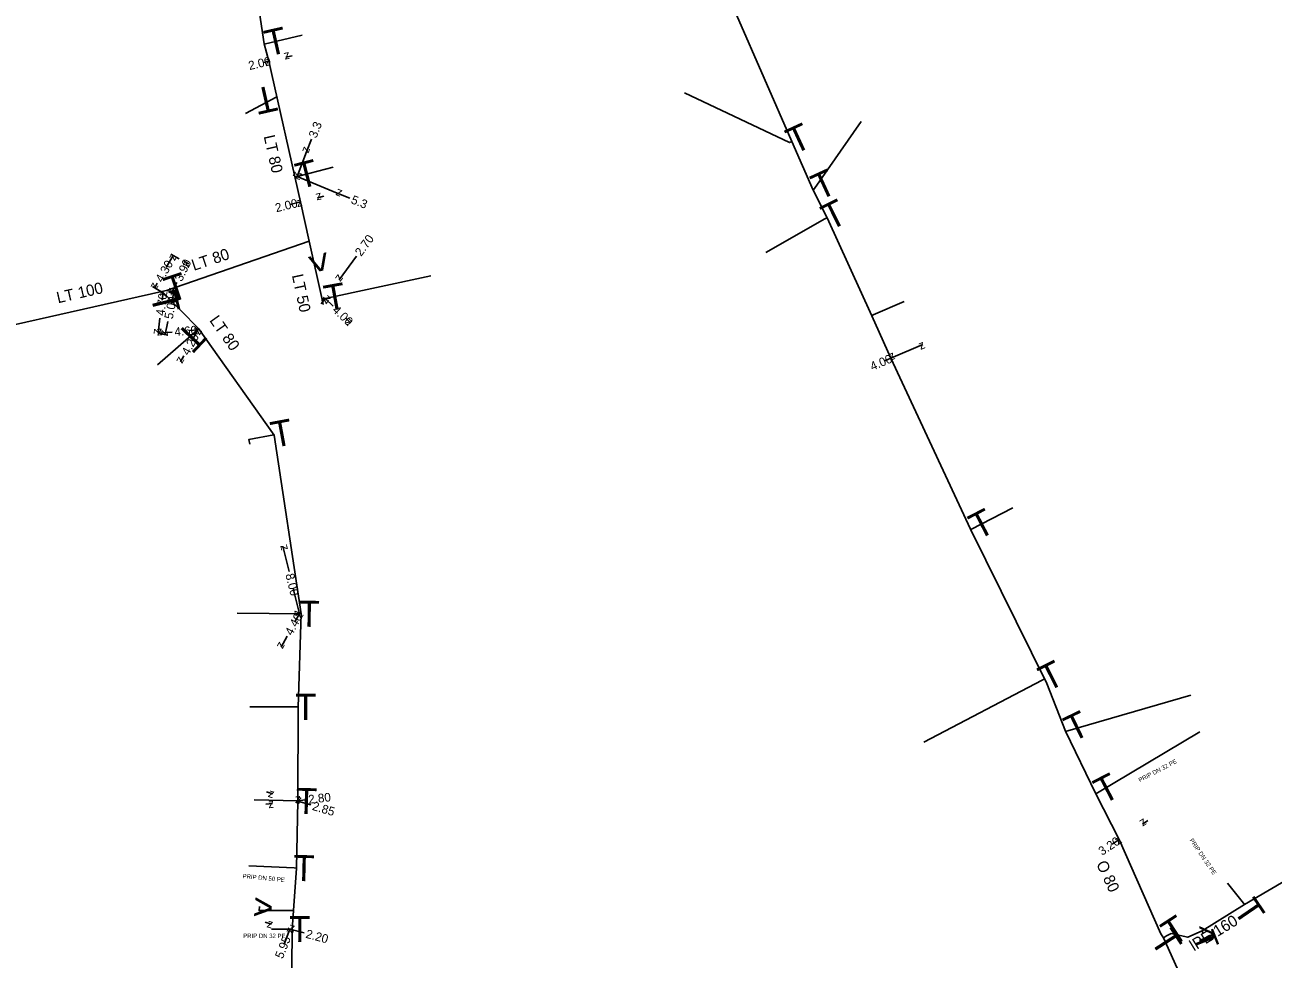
# Model space of a CAD drawing. Extents: x -634006 to -632185, y -1101085 to -1098649.
# Drawn here: x -633160.5 to -633016.8, y -1099032.9 to -1098925.4 of the extents above; entities that cross this region are included whole.
import ezdxf

# ---------------------------------------------------------------- set-up
doc = ezdxf.new("R2010")
doc.units = 0
for name, color, linetype in [('VP Hydrant', 7, 'Continuous'), ('VP Kótování', 7, 'Continuous'), ('VP Popis přípojky', 7, 'Continuous'), ('VP Přípojka', 7, 'Continuous'), ('VP Řad', 7, 'Continuous'), ('VP Řad - popis', 7, 'Continuous'), ('VP Šoupě', 7, 'Continuous')]:
    doc.layers.add(name, color=color, linetype=linetype)

msp = doc.modelspace()

# ---------------------------------------------------------------- linework, layer by layer
at = {"layer": 'VP Kótování'}
for points in [[(-633133.01, -1098929.7), (-633132.4, -1098929.56)], [(-633129.72, -1098928.93), (-633130.45, -1098929.1)], [(-633128.04, -1098939.98), (-633127.48, -1098938.55)], [(-633129.13, -1098942.84), (-633128.04, -1098939.98)], [(-633129.13, -1098942.84), (-633124.52, -1098944.75)], [(-633129.92, -1098946.06), (-633128.73, -1098945.77)], [(-633126.06, -1098945.12), (-633126.79, -1098945.3)], [(-633124.52, -1098944.75), (-633123.06, -1098945.33)], [(-633144.21, -1098953.33), (-633143.42, -1098951.93)], [(-633142.72, -1098952.32), (-633143.68, -1098951.78)], [(-633142.19, -1098952.6), (-633141.6, -1098952.89)], [(-633122.31, -1098952.01), (-633124.31, -1098954.73)], [(-633144.83, -1098956.07), (-633145.79, -1098955.52)], [(-633145.23, -1098955.13), (-633145.53, -1098955.67)], [(-633142.99, -1098955.06), (-633143.58, -1098956.26)], [(-633144.87, -1098956.21), (-633144.87, -1098956.21)], [(-633144.68, -1098957.09), (-633144.57, -1098956.21)], [(-633143.9, -1098956.1), (-633143.31, -1098956.39)], [(-633143.88, -1098956.03), (-633143.05, -1098956.19)], [(-633143.6, -1098957.45), (-633143.34, -1098956.14)], [(-633126.35, -1098957.51), (-633125.91, -1098956.9)], [(-633124.99, -1098957.77), (-633125.91, -1098956.9)], [(-633144.93, -1098959.15), (-633145.14, -1098960.88)], [(-633144.01, -1098959.52), (-633144.31, -1098961.04)], [(-633123.54, -1098959.16), (-633123.01, -1098959.66)], [(-633143.5, -1098960.74), (-633145.14, -1098960.88)], [(-633144.85, -1098960.94), (-633144.02, -1098961.1)], [(-633144.84, -1098960.88), (-633144.84, -1098960.88)], [(-633141.51, -1098960.57), (-633140.56, -1098960.49)], [(-633141.24, -1098961.77), (-633140.56, -1098960.49)], [(-633060.77, -1098963.75), (-633057.1, -1098962.16)], [(-633142.18, -1098963.5), (-633142.55, -1098964.19)], [(-633061.49, -1098964.06), (-633060.77, -1098963.75)], [(-633130.06, -1098988.31), (-633130.78, -1098985.4)], [(-633129.58, -1098990.26), (-633128.87, -1098993.17)], [(-633129.34, -1098994.02), (-633128.87, -1098993.17)], [(-633130.28, -1098995.75), (-633130.98, -1098997.03)], [(-633132.65, -1099013.69), (-633131.93, -1099013.9)], [(-633128.09, -1099014.59), (-633129.2, -1099014.71)], [(-633127.57, -1099015.19), (-633129.2, -1099014.71)], [(-633132.73, -1099015.1), (-633131.98, -1099015.02)], [(-633031.2, -1099016.98), (-633031.83, -1099017.39)], [(-633035.31, -1099019.69), (-633034.5, -1099019.15)], [(-633132.8, -1099028.7), (-633132.08, -1099028.9)], [(-633130.64, -1099031.21), (-633129.96, -1099029.48)], [(-633128.33, -1099029.91), (-633129.96, -1099029.48)]]:
    msp.add_lwpolyline(points, dxfattribs=at)
at = {"layer": 'VP Přípojka'}
for p, q in [((-633040.67, -1099006.72), (-633026.25, -1099002.54)), ((-633037.2, -1099013.92), (-633025.21, -1099006.78))]:
    msp.add_line(p, q, dxfattribs=at)
for points in [[(-633132.92, -1098927.6), (-633128.56, -1098926.55)], [(-633131.47, -1098933.66), (-633135.07, -1098935.58)], [(-633072.18, -1098938.82), (-633072.46, -1098938.93), (-633084.55, -1098933.22)], [(-633069.72, -1098944.4), (-633069.56, -1098944.23), (-633064.19, -1098936.51)], [(-633129.38, -1098942.91), (-633124.97, -1098941.78)], [(-633068.12, -1098947.61), (-633068.38, -1098947.72), (-633075.16, -1098951.57)], [(-633126.23, -1098956.97), (-633113.73, -1098954.29)], [(-633062.99, -1098958.87), (-633062.83, -1098958.78), (-633059.25, -1098957.22)], [(-633140.44, -1098960.39), (-633145.19, -1098964.52)], [(-633131.8, -1098972.56), (-633134.68, -1098973.1), (-633134.57, -1098973.67)], [(-633051.59, -1098983.47), (-633046.75, -1098980.97)], [(-633128.68, -1098993.17), (-633136.04, -1098993.1)], [(-633043.09, -1099000.68), (-633043.36, -1099000.83), (-633056.97, -1099007.96)], [(-633129.03, -1099003.89), (-633134.57, -1099003.89)], [(-633129.05, -1099014.71), (-633134.08, -1099014.58)], [(-633129.22, -1099022.46), (-633129.47, -1099022.43), (-633134.68, -1099022.18)], [(-633020.06, -1099026.65), (-633020.17, -1099026.51), (-633022.03, -1099024.19)], [(-633133.45, -1099026.89), (-633133.51, -1099027.35), (-633129.53, -1099027.35)], [(-633129.7, -1099029.48), (-633132.09, -1099029.47)], [(-633024.94, -1099029.67), (-633024.85, -1099029.9), (-633024.8, -1099030)]]:
    msp.add_lwpolyline(points, dxfattribs=at)
at = {"layer": 'VP Řad'}
for points in [[(-633060.77, -1098963.75), (-633062.99, -1098958.87), (-633068.12, -1098947.61), (-633069.72, -1098944.4), (-633072.18, -1098938.82), (-633078.56, -1098924.23), (-633080.56, -1098917.23), (-633082.39, -1098913.02), (-633083.95, -1098906.52), (-633085.07, -1098902.44), (-633086.4, -1098895.32), (-633086.9, -1098890.56), (-633087.38, -1098879.75), (-633087.43, -1098878.57), (-633092.08, -1098878.87), (-633092.36, -1098878.86)], [(-633127.73, -1098950.29), (-633128.73, -1098945.77), (-633132.4, -1098929.56), (-633132.93, -1098927.58), (-633133.71, -1098922.44), (-633136.86, -1098910.96), (-633137.68, -1098903.96), (-633139.34, -1098887.1), (-633137.24, -1098886.55), (-633127.67, -1098884.06)], [(-633144.7, -1098956.07), (-633144.17, -1098955.97), (-633127.73, -1098950.29)], [(-633126.15, -1098957.56), (-633126.23, -1098957.01), (-633127.73, -1098950.29)], [(-633144.7, -1098956.07), (-633173.33, -1098962.53), (-633173.72, -1098962.62), (-633190.05, -1098965.62)], [(-633134.63, -1099077.16), (-633134.29, -1099076.38), (-633133.33, -1099070.09), (-633129.87, -1099047.29), (-633129.7, -1099029.51), (-633129.53, -1099027.35), (-633129.22, -1099022.46), (-633129.05, -1099014.72), (-633129.03, -1099003.92), (-633128.67, -1098993.18), (-633131.77, -1098972.61), (-633140.49, -1098960.32), (-633144.57, -1098956.21), (-633144.7, -1098956.07)], [(-633029.41, -1099030.48), (-633029.69, -1099030.02), (-633034.5, -1099019.15), (-633037.2, -1099013.91), (-633040.69, -1099006.69), (-633042.82, -1099001.19), (-633051.6, -1098983.45), (-633060.77, -1098963.75)], [(-632895.78, -1098965.23), (-632896.99, -1098965.82), (-632903.66, -1098969.02), (-632910.32, -1098972.23), (-632926.75, -1098980.4), (-632933.45, -1098983.65), (-632951.54, -1098991.48), (-632970.71, -1099000.65), (-632972.54, -1099001.38), (-632975.54, -1099001.12), (-632981.27, -1099003.8), (-632996.66, -1099012.39), (-632997.06, -1099012.64), (-633008.69, -1099020), (-633015.83, -1099024.17), (-633020.06, -1099026.65), (-633024.94, -1099029.67), (-633026.6, -1099030.42), (-633028.5, -1099030), (-633029.06, -1099030.27), (-633029.41, -1099030.48)], [(-633029.41, -1099030.48), (-633024.36, -1099041.64), (-633024.08, -1099042.08)]]:
    msp.add_lwpolyline(points, dxfattribs=at)

# ---------------------------------------------------------------- texts
at = {"layer": 'VP Hydrant'}
for rotation, p in [(284.8388, (-633128.27, -1098952.01)), (355.3328, (-633134.32, -1099028.32))]:
    msp.add_text('>', height=3, rotation=rotation, dxfattribs=at).set_placement(p)
msp.add_text('>', height=2.5, dxfattribs=at).set_placement((-633025.42, -1099031.25))
at = {"layer": 'VP Kótování'}
for s, rotation, p in [('z', 193.2438, (-633130.08, -1098928.5)), ('2.00', 13.2438, (-633134.61, -1098930.59)), ('z', 13.2438, (-633132.77, -1098930.16)), ('3.3', 68.5585, (-633126.92, -1098938.5)), ('z', 248.5584, (-633128.32, -1098939.33)), ('z', 249.2205, (-633129.42, -1098942.2)), ('z', 157.4986, (-633128.47, -1098942.57)), ('z', 158.2323, (-633123.87, -1098944.47)), ('2.00', 13.5983, (-633131.52, -1098946.96)), ('z', 13.5983, (-633129.1, -1098946.37)), ('z', 193.5983, (-633126.42, -1098944.7)), ('5.3', 338.2323, (-633123.01, -1098945.89)), ('2.70', 53.6651, (-633121.76, -1098952.1)), ('4.30', 60.5544, (-633144.64, -1098955.11)), ('z', 60.5544, (-633143.23, -1098952.61)), ('3.90', 63.9805, (-633142.41, -1098955.01)), ('z', 63.9805, (-633141.64, -1098953.43)), ('z', 233.6651, (-633124.41, -1098954.03)), ('z', 240.5544, (-633145.72, -1098954.99)), ('z', 243.9805, (-633143.81, -1098955.59)), ('z', 78.8181, (-633142.95, -1098956.72)), ('4.70', 83.073, (-633144.4, -1098958.91)), ('z', 83.073, (-633144.14, -1098956.77)), ('5.00', 78.8181, (-633143.46, -1098959.32)), ('z', 53.6651, (-633125.8, -1098957.6)), ('z', 136.4081, (-633125.2, -1098956.88)), ('4.00', 316.408, (-633125.16, -1098958.31)), ('4.60', 4.8257, (-633143.21, -1098961.22)), ('z', 4.8257, (-633141.01, -1098961.03)), ('z', 61.6595, (-633140.35, -1098961.17)), ('z', 316.4081, (-633123.72, -1098959.68)), ('z', 263.073, (-633145.58, -1098960.32)), ('z', 184.8257, (-633144.68, -1098960.34)), ('z', 258.8181, (-633144.71, -1098960.46)), ('4.20', 61.6595, (-633141.62, -1098963.52)), ('z', 203.3923, (-633060.51, -1098963.09)), ('z', 23.3923, (-633057.36, -1098962.82)), ('z', 241.6595, (-633142.75, -1098963.51)), ('4.00', 23.3923, (-633062.91, -1098965.22)), ('z', 103.8139, (-633130.18, -1098985.77)), ('8.00', 283.8139, (-633130.49, -1098988.67)), ('4.40', 61.35, (-633129.72, -1098995.77)), ('z', 283.8139, (-633129.47, -1098992.8)), ('z', 61.35, (-633128.67, -1098993.85)), ('z', 241.3501, (-633131.18, -1098996.35)), ('z', 343.5106, (-633132.55, -1099014.24)), ('z', 6.3763, (-633132.42, -1099015.57)), ('z', 163.5106, (-633128.58, -1099014.37)), ('z', 186.3764, (-633128.76, -1099014.16)), ('2.80', 6.3763, (-633127.79, -1099015.05)), ('2.85', 343.5106, (-633127.47, -1099015.74)), ('z', 213.4218, (-633031.69, -1099016.7)), ('3.20', 33.4218, (-633036.47, -1099021.05)), ('z', 33.4218, (-633034.64, -1099019.84)), ('z', 344.8522, (-633132.69, -1099029.25)), ('z', 68.4668, (-633129.67, -1099030.12)), ('z', 164.8522, (-633129.34, -1099029.12)), ('5.95', 68.4668, (-633130.79, -1099032.96)), ('2.20', 344.8522, (-633128.22, -1099030.46))]:
    msp.add_text(s, height=1, rotation=rotation, dxfattribs=at).set_placement(p)
at = {"layer": 'VP Popis přípojky'}
for s, rotation, p in [('PRIP DN 32 PE', 27.7521, (-633032.11, -1099012.59)), ('PRIP DN 32 PE', 304.3882, (-633026.43, -1099019.26)), ('PRIP DN 50 PE', 354.5583, (-633135.43, -1099023.61)), ('PRIP DN 32 PE', 359.8318, (-633135.34, -1099030.5))]:
    msp.add_text(s, height=0.5, rotation=rotation, dxfattribs=at).set_placement(p)
at = {"layer": 'VP Řad - popis'}
for s, rotation, p in [('LT 80', 282.7318, (-633132.99, -1098938.21)), ('LT 80', 18.5503, (-633141.02, -1098953.71)), ('LT 50', 282.1199, (-633129.74, -1098954.22)), ('LT 100', 12.812, (-633156.66, -1098957.44)), ('LT 80', 305.3764, (-633139.28, -1098959.41)), ('O 80', 294.9697, (-633037.17, -1099021.96)), ('lPE 160', 31.5805, (-633025.89, -1099032.06))]:
    msp.add_text(s, height=1.3, rotation=rotation, dxfattribs=at).set_placement(p)
at = {"layer": 'VP Šoupě'}
for height, rotation, p in [(3, 12.7319, (-633132.47, -1098929.03)), (3, 192.7318, (-633131.88, -1098932.27)), (3, 24.8126, (-633071.92, -1098940.33)), (3, 14.3604, (-633128.85, -1098944.32)), (3, 24.8126, (-633069.02, -1098945.63)), (3, 26.2586, (-633067.8, -1098949.11)), (3, 18.5496, (-633143.78, -1098957.43)), (3, 283.7382, (-633146.05, -1098956.48)), (3, 10.2158, (-633125.73, -1098958.39)), (3, 226.7707, (-633141.58, -1098959.4)), (3, 10.5945, (-633131.84, -1098974.09)), (3, 27.3201, (-633050.75, -1098984.73)), (3, 359.463, (-633128.98, -1098994.67)), (3, 26.7325, (-633042.77, -1099002.21)), (3, 359.9897, (-633129.37, -1099005.39)), (3, 25.7569, (-633039.88, -1099008)), (3, 27.2954, (-633036.37, -1099015.18)), (3, 358.4836, (-633129.33, -1099016.21)), (3, 358.6046, (-633129.6, -1099023.93)), (3, 304.3881, (-633021.46, -1099027.28)), (3, 32.9769, (-633028.35, -1099031.59)), (3, 359.8318, (-633130.05, -1099030.97)), (3, 302.9769, (-633031, -1099030.76)), (2.5, 291.8858, (-633026.04, -1099030.29))]:
    msp.add_text('T', height=height, rotation=rotation, dxfattribs=at).set_placement(p)

doc.saveas('drawing.dxf')
